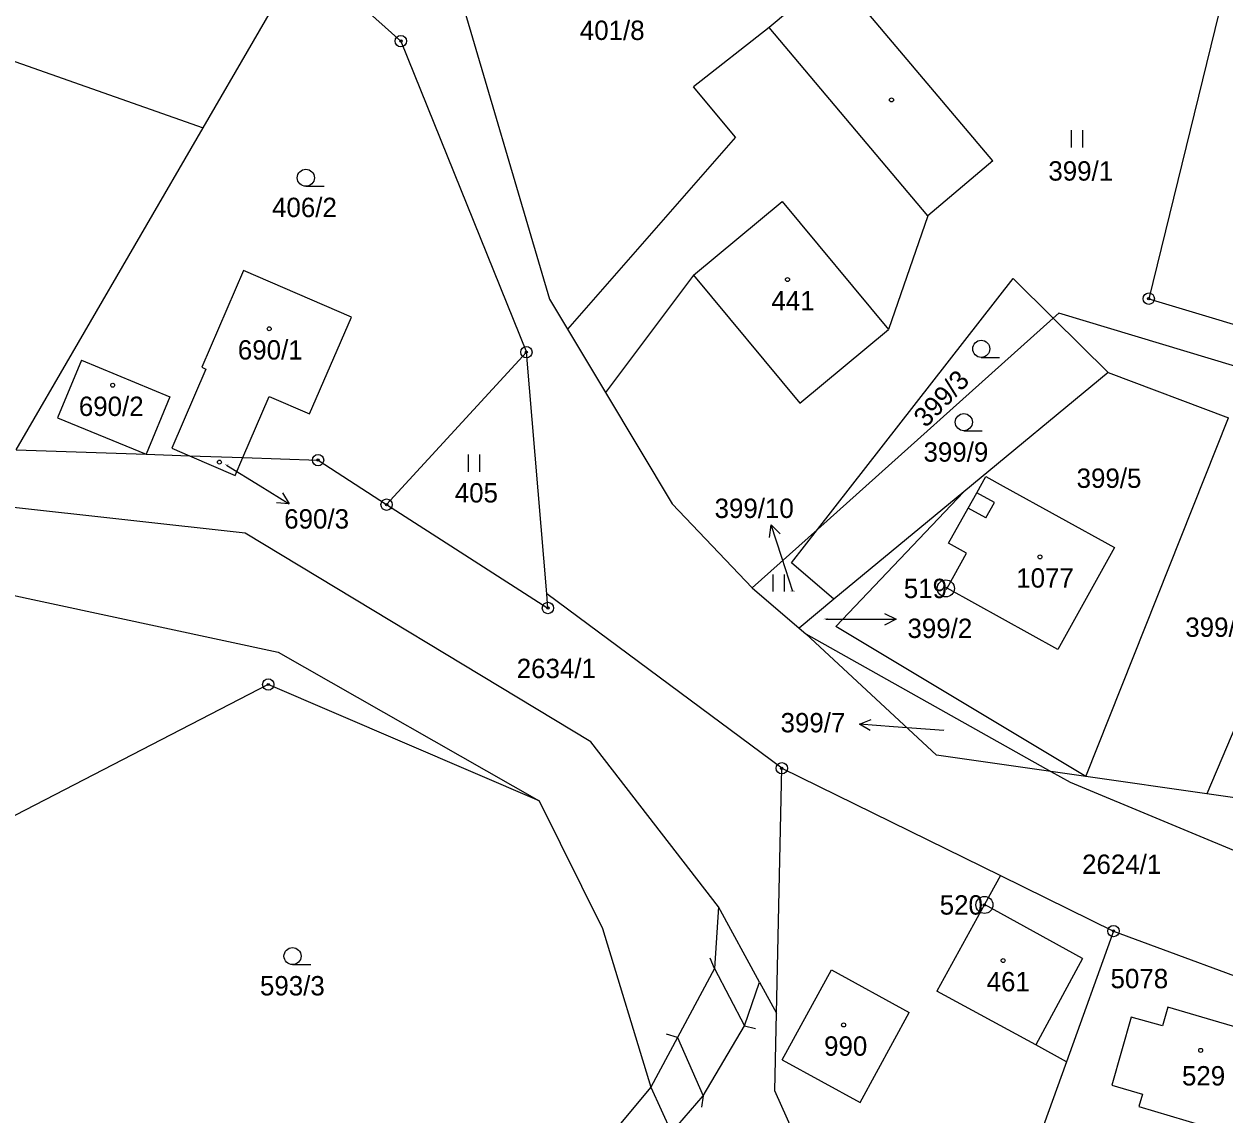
# Model space of a CAD drawing. Extents: x -439246 to -433691, y -1130252 to -1121148.
# Drawn here: x -437614.4 to -437509, y -1124136.2 to -1124040.5 of the extents above; entities that cross this region are included whole.
import ezdxf

# ---------------------------------------------------------------- set-up
doc = ezdxf.new("R2010")
doc.units = 0
for name, color, linetype in [('Vrstva 1', 7, 'Continuous'), ('Vrstva 16', 7, 'Continuous'), ('Vrstva 17', 7, 'Continuous'), ('Vrstva 18', 7, 'Continuous'), ('Vrstva 19', 7, 'Continuous'), ('Vrstva 24', 7, 'Continuous'), ('Vrstva 25', 7, 'Continuous'), ('Vrstva 26', 7, 'Continuous'), ('Vrstva 3', 7, 'Continuous'), ('Vrstva 37', 7, 'Continuous'), ('Vrstva 4', 7, 'Continuous')]:
    doc.layers.add(name, color=color, linetype=linetype)

msp = doc.modelspace()

# ---------------------------------------------------------------- linework, layer by layer
at = {"layer": 'Vrstva 1'}
for points in [[(-437507.31, -1124030.55), (-437515.65, -1124064.59)], [(-437598.67, -1124049.6), (-437589.83, -1124034.37)], [(-437589.83, -1124034.37), (-437581.3, -1124041.99)], [(-437576.65, -1124036.12), (-437568.26, -1124064.63)], [(-437543.27, -1124035.99), (-437548.98, -1124040.81)], [(-437529.34, -1124052.5), (-437543.27, -1124035.99)], [(-437622.36, -1124041.27), (-437598.67, -1124049.6)], [(-437548.98, -1124040.81), (-437555.6, -1124045.99)], [(-437581.3, -1124041.99), (-437570.28, -1124069.28)], [(-437551.93, -1124050.43), (-437555.6, -1124045.99)], [(-437615.06, -1124077.85), (-437598.67, -1124049.6)], [(-437551.93, -1124050.43), (-437566.66, -1124067.25)], [(-437529.34, -1124052.5), (-437535.05, -1124057.32)], [(-437535.05, -1124057.32), (-437538.5, -1124067.29)], [(-437595.11, -1124062.11), (-437598.78, -1124070.6)], [(-437585.63, -1124066.21), (-437595.11, -1124062.11)], [(-437555.6, -1124062.52), (-437563.34, -1124072.82)], [(-437555.6, -1124062.52), (-437546.27, -1124073.75)], [(-437544.73, -1124084.84), (-437527.55, -1124062.81)], [(-437527.55, -1124062.81), (-437524.03, -1124066.3)], [(-437568.26, -1124064.63), (-437566.66, -1124067.25)], [(-437515.65, -1124064.59), (-437476.75, -1124076.28)], [(-437589.32, -1124074.7), (-437585.63, -1124066.21)], [(-437524.03, -1124066.3), (-437544.73, -1124084.84)], [(-437523.55, -1124065.87), (-437524.03, -1124066.3)], [(-437524.03, -1124066.3), (-437519.22, -1124071.08)], [(-437479.06, -1124079.25), (-437523.55, -1124065.87)], [(-437566.66, -1124067.25), (-437563.34, -1124072.82)], [(-437546.27, -1124073.75), (-437538.5, -1124067.29)], [(-437609.35, -1124069.99), (-437611.43, -1124075.03)], [(-437609.35, -1124069.99), (-437601.59, -1124073.2)], [(-437570.28, -1124069.28), (-437582.55, -1124082.66)], [(-437568.49, -1124090.49), (-437570.28, -1124069.28)], [(-437598.42, -1124070.76), (-437601.42, -1124077.69)], [(-437598.78, -1124070.6), (-437598.42, -1124070.76)], [(-437519.22, -1124071.08), (-437531.88, -1124081.54)], [(-437519.22, -1124071.08), (-437508.64, -1124075.04)], [(-437601.59, -1124073.2), (-437603.67, -1124078.24)], [(-437595.18, -1124078.52), (-437592.86, -1124073.17)], [(-437592.86, -1124073.17), (-437589.32, -1124074.7)], [(-437563.34, -1124072.82), (-437557.48, -1124082.59)], [(-437611.43, -1124075.03), (-437603.67, -1124078.24)], [(-437521.17, -1124106.51), (-437508.64, -1124075.04)], [(-437615.06, -1124077.85), (-437603.67, -1124078.24)], [(-437603.67, -1124078.24), (-437599.85, -1124078.37)], [(-437601.42, -1124077.69), (-437599.85, -1124078.37)], [(-437599.85, -1124078.37), (-437595.86, -1124080.1)], [(-437599.85, -1124078.37), (-437595.18, -1124078.52)], [(-437595.86, -1124080.1), (-437595.18, -1124078.52)], [(-437595.18, -1124078.52), (-437588.57, -1124078.75)], [(-437588.57, -1124078.75), (-437582.55, -1124082.66)], [(-437498.29, -1124079.18), (-437510.55, -1124108.03)], [(-437594.98, -1124085.15), (-437636.74, -1124080.53)], [(-437530.75, -1124081.63), (-437529.96, -1124080.18)], [(-437529.96, -1124080.18), (-437528.42, -1124081.05)], [(-437531.88, -1124081.54), (-437543.28, -1124090.96)], [(-437543.13, -1124093.35), (-437531.88, -1124081.54)], [(-437531.5, -1124082.97), (-437530.75, -1124081.63)], [(-437528.42, -1124081.05), (-437518.65, -1124086.42)], [(-437582.55, -1124082.66), (-437568.39, -1124091.73)], [(-437557.48, -1124082.59), (-437550.45, -1124089.96)], [(-437533.22, -1124086.03), (-437531.5, -1124082.97)], [(-437564.63, -1124103.48), (-437594.98, -1124085.15)], [(-437544.73, -1124084.84), (-437550.45, -1124089.96)], [(-437547.01, -1124087.76), (-437544.73, -1124084.84)], [(-437636.68, -1124086.05), (-437592.08, -1124095.61)], [(-437533.35, -1124089.99), (-437531.65, -1124086.91)], [(-437531.65, -1124086.91), (-437533.22, -1124086.03)], [(-437518.65, -1124086.42), (-437523.64, -1124095.37)], [(-437543.28, -1124090.96), (-437547.01, -1124087.76)], [(-437550.45, -1124089.96), (-437546.33, -1124093.49)], [(-437523.64, -1124095.37), (-437533.35, -1124089.99)], [(-437547.86, -1124105.79), (-437568.49, -1124090.49)], [(-437568.39, -1124091.73), (-437568.49, -1124090.49)], [(-437543.28, -1124090.96), (-437546.33, -1124093.49)], [(-437546.33, -1124093.49), (-437545.76, -1124093.98)], [(-437534.29, -1124104.64), (-437545.76, -1124093.98)], [(-437545.76, -1124093.98), (-437524.24, -1124106.07)], [(-437521.17, -1124106.51), (-437543.13, -1124093.35)], [(-437592.08, -1124095.61), (-437569.16, -1124108.65)], [(-437592.94, -1124098.44), (-437619.4, -1124112.1)], [(-437569.16, -1124108.65), (-437592.94, -1124098.44)], [(-437553.43, -1124117.95), (-437564.63, -1124103.48)], [(-437524.24, -1124106.07), (-437534.29, -1124104.64)], [(-437548.32, -1124127.27), (-437547.86, -1124105.79)], [(-437547.86, -1124105.79), (-437528.66, -1124115.21)], [(-437524.24, -1124106.07), (-437522.55, -1124107.02)], [(-437521.17, -1124106.51), (-437524.24, -1124106.07)], [(-437510.55, -1124108.03), (-437521.17, -1124106.51)], [(-437522.55, -1124107.02), (-437497.19, -1124117.57)], [(-437569.16, -1124108.65), (-437563.6, -1124119.86)], [(-437496.29, -1124110.07), (-437510.55, -1124108.03)], [(-437528.66, -1124115.21), (-437530.07, -1124117.73)], [(-437528.66, -1124115.21), (-437518.74, -1124120.07)], [(-437549.81, -1124124.55), (-437553.43, -1124117.95)], [(-437530.07, -1124117.73), (-437534.25, -1124125.36)], [(-437563.6, -1124119.86), (-437559.36, -1124133.76)], [(-437518.74, -1124120.07), (-437522.88, -1124131.56)], [(-437518.74, -1124120.07), (-437503.2, -1124125.8)], [(-437547.83, -1124131.37), (-437543.51, -1124123.48)], [(-437543.51, -1124123.48), (-437536.67, -1124127.22)], [(-437549.81, -1124124.55), (-437548.32, -1124127.27)], [(-437525.56, -1124130.06), (-437534.25, -1124125.36)], [(-437504.32, -1124129.59), (-437513.96, -1124126.75), (-437514.44, -1124128.38), (-437517.19, -1124127.63), (-437518.89, -1124133.58), (-437516.21, -1124134.37), (-437516.53, -1124135.47), (-437506.89, -1124138.32)], [(-437548.46, -1124134.08), (-437548.32, -1124127.27)], [(-437540.99, -1124135.12), (-437536.67, -1124127.22)], [(-437522.88, -1124131.56), (-437525.56, -1124130.06)], [(-437547.83, -1124131.37), (-437540.99, -1124135.12)], [(-437522.88, -1124131.56), (-437524.89, -1124137.13)], [(-437559.36, -1124133.76), (-437565.4, -1124141.01)], [(-437559.36, -1124133.76), (-437557.54, -1124137.76)], [(-437534.8, -1124164.61), (-437548.46, -1124134.08)]]:
    msp.add_lwpolyline(points, dxfattribs=at)
at = {"layer": 'Vrstva 16'}
for p, q in [((-437593.66, -1124081.01), (-437591.11, -1124082.58)), ((-437547.86, -1124087.29), (-437548.78, -1124084.44)), ((-437540.83, -1124092.72), (-437537.83, -1124092.72)), ((-437538.06, -1124102.15), (-437541.05, -1124101.92))]:
    msp.add_line(p, q, dxfattribs=at)
for points in [[(-437596.6, -1124079.19), (-437593.66, -1124081.01)], [(-437591.7, -1124081.63), (-437591.11, -1124082.58), (-437592.22, -1124082.49)], [(-437548.95, -1124085.54), (-437548.78, -1124084.44), (-437548, -1124085.23)], [(-437546.89, -1124090.29), (-437547.86, -1124087.29)], [(-437543.99, -1124092.72), (-437540.83, -1124092.72)], [(-437538.83, -1124092.22), (-437537.83, -1124092.72), (-437538.83, -1124093.22)], [(-437540.09, -1124102.49), (-437541.05, -1124101.92), (-437540.02, -1124101.5)], [(-437533.65, -1124102.49), (-437538.06, -1124102.15)]]:
    msp.add_lwpolyline(points, dxfattribs=at)
at = {"layer": 'Vrstva 24'}
for centre, radius in [((-437581.3, -1124041.99), 0.5), ((-437581.3, -1124041.99), 0.1), ((-437515.65, -1124064.59), 0.5), ((-437515.65, -1124064.59), 0.1), ((-437570.28, -1124069.28), 0.5), ((-437570.28, -1124069.28), 0.1), ((-437588.57, -1124078.75), 0.5), ((-437588.57, -1124078.75), 0.1), ((-437582.55, -1124082.66), 0.5), ((-437582.55, -1124082.66), 0.1), ((-437533.46, -1124090.01), 0.75), ((-437533.46, -1124090.01), 0.1), ((-437568.39, -1124091.73), 0.5), ((-437568.39, -1124091.73), 0.1), ((-437592.94, -1124098.44), 0.5), ((-437592.94, -1124098.44), 0.1), ((-437547.86, -1124105.79), 0.5), ((-437547.86, -1124105.79), 0.1), ((-437530.07, -1124117.78), 0.75), ((-437530.07, -1124117.78), 0.1), ((-437518.74, -1124120.07), 0.5), ((-437518.74, -1124120.07), 0.1)]:
    msp.add_circle(centre, radius, dxfattribs=at)
at = {"layer": 'Vrstva 25'}
for p, q in [((-437522.42, -1124051.31), (-437522.42, -1124049.81)), ((-437521.42, -1124051.31), (-437521.42, -1124049.81)), ((-437589.64, -1124054.73), (-437588.04, -1124054.73)), ((-437530.35, -1124069.74), (-437528.75, -1124069.74)), ((-437531.88, -1124076.17), (-437530.28, -1124076.17)), ((-437575.37, -1124079.77), (-437575.37, -1124078.27)), ((-437574.37, -1124079.77), (-437574.37, -1124078.27)), ((-437548.62, -1124090.29), (-437548.62, -1124088.79)), ((-437547.62, -1124090.29), (-437547.62, -1124088.79)), ((-437590.81, -1124123.02), (-437589.21, -1124123.02))]:
    msp.add_line(p, q, dxfattribs=at)
for centre, radius in [((-437538.23, -1124047.15), 0.175), ((-437589.64, -1124053.98), 0.75), ((-437547.36, -1124062.91), 0.175), ((-437592.86, -1124067.23), 0.175), ((-437530.35, -1124068.99), 0.75), ((-437606.6, -1124072.18), 0.175), ((-437531.88, -1124075.42), 0.75), ((-437597.23, -1124078.93), 0.175), ((-437525.2, -1124087.24), 0.175), ((-437590.81, -1124122.27), 0.75), ((-437528.43, -1124122.66), 0.175), ((-437542.43, -1124128.31), 0.175), ((-437511.09, -1124130.54), 0.175)]:
    msp.add_circle(centre, radius, dxfattribs=at)
at = {"layer": 'Vrstva 26'}
for p, q in [((-437553.76, -1124123.37), (-437554.15, -1124122.45)), ((-437551.14, -1124128.39), (-437550.17, -1124128.61)), ((-437557.01, -1124129.4), (-437557.97, -1124129.13)), ((-437554.75, -1124134.52), (-437554.91, -1124135.51))]:
    msp.add_line(p, q, dxfattribs=at)
at = {"layer": 'Vrstva 3'}
for points in [[(-437555.6, -1124062.52), (-437547.84, -1124056.06)], [(-437547.84, -1124056.06), (-437538.5, -1124067.29)], [(-437595.11, -1124062.11), (-437598.78, -1124070.6)], [(-437585.63, -1124066.21), (-437595.11, -1124062.11)], [(-437555.6, -1124062.52), (-437546.27, -1124073.75)], [(-437589.32, -1124074.7), (-437585.63, -1124066.21)], [(-437546.27, -1124073.75), (-437538.5, -1124067.29)], [(-437609.35, -1124069.99), (-437611.43, -1124075.03)], [(-437609.35, -1124069.99), (-437601.59, -1124073.2)], [(-437598.42, -1124070.76), (-437601.42, -1124077.69)], [(-437598.78, -1124070.6), (-437598.42, -1124070.76)], [(-437601.59, -1124073.2), (-437603.67, -1124078.24)], [(-437595.18, -1124078.52), (-437592.86, -1124073.17)], [(-437592.86, -1124073.17), (-437589.32, -1124074.7)], [(-437611.43, -1124075.03), (-437603.67, -1124078.24)], [(-437601.42, -1124077.69), (-437599.85, -1124078.37)], [(-437599.85, -1124078.37), (-437595.86, -1124080.1)], [(-437595.86, -1124080.1), (-437595.18, -1124078.52)], [(-437530.75, -1124081.63), (-437529.96, -1124080.18)], [(-437529.96, -1124080.18), (-437528.42, -1124081.05)], [(-437529.2, -1124082.48), (-437530.75, -1124081.63)], [(-437528.42, -1124081.05), (-437518.65, -1124086.42)], [(-437529.95, -1124083.83), (-437529.2, -1124082.48)], [(-437533.22, -1124086.03), (-437531.5, -1124082.97)], [(-437529.95, -1124083.83), (-437531.5, -1124082.97)], [(-437533.35, -1124089.99), (-437531.65, -1124086.91)], [(-437531.65, -1124086.91), (-437533.22, -1124086.03)], [(-437518.65, -1124086.42), (-437523.64, -1124095.37)], [(-437523.64, -1124095.37), (-437533.35, -1124089.99)], [(-437530.07, -1124117.73), (-437534.25, -1124125.36)], [(-437521.47, -1124122.49), (-437530.07, -1124117.73)], [(-437521.47, -1124122.49), (-437525.56, -1124130.06)], [(-437547.83, -1124131.37), (-437543.51, -1124123.48)], [(-437543.51, -1124123.48), (-437536.67, -1124127.22)], [(-437525.56, -1124130.06), (-437534.25, -1124125.36)], [(-437504.32, -1124129.59), (-437513.96, -1124126.75), (-437514.44, -1124128.38), (-437517.19, -1124127.63), (-437518.89, -1124133.58), (-437516.21, -1124134.37), (-437516.53, -1124135.47), (-437506.89, -1124138.32)], [(-437540.99, -1124135.12), (-437536.67, -1124127.22)], [(-437547.83, -1124131.37), (-437540.99, -1124135.12)]]:
    msp.add_lwpolyline(points, dxfattribs=at)
at = {"layer": 'Vrstva 37'}
for centre in [(-437547.36, -1124062.91), (-437592.86, -1124067.23), (-437606.6, -1124072.18), (-437525.2, -1124087.24), (-437528.43, -1124122.66), (-437542.43, -1124128.31), (-437511.09, -1124130.54)]:
    msp.add_circle(centre, 0.175, dxfattribs=at)
at = {"layer": 'Vrstva 4'}
for points in [[(-437535.05, -1124057.32), (-437548.98, -1124040.81)], [(-437555.6, -1124062.52), (-437547.84, -1124056.06)], [(-437547.84, -1124056.06), (-437538.5, -1124067.29)], [(-437529.2, -1124082.48), (-437530.75, -1124081.63)], [(-437529.95, -1124083.83), (-437529.2, -1124082.48)], [(-437529.95, -1124083.83), (-437531.5, -1124082.97)], [(-437553.43, -1124117.95), (-437553.76, -1124123.37)], [(-437521.47, -1124122.49), (-437530.07, -1124117.73)], [(-437521.47, -1124122.49), (-437525.56, -1124130.06)], [(-437553.76, -1124123.37), (-437557.01, -1124129.4)], [(-437553.76, -1124123.37), (-437551.14, -1124128.39)], [(-437551.14, -1124128.39), (-437549.81, -1124124.55)], [(-437554.75, -1124134.52), (-437551.14, -1124128.39)], [(-437557.01, -1124129.4), (-437559.36, -1124133.76)], [(-437557.01, -1124129.4), (-437554.75, -1124134.52)], [(-437557.54, -1124137.76), (-437554.75, -1124134.52)]]:
    msp.add_lwpolyline(points, dxfattribs=at)

# ---------------------------------------------------------------- texts
at = {"layer": 'Vrstva 16'}
for s, p in [('399/10', (-437553.76, -1124083.83)), ('690/3', (-437591.54, -1124084.76)), ('399/2', (-437536.83, -1124094.36)), ('399/7', (-437547.97, -1124102.64)), ('2624/1', (-437521.5, -1124115.06))]:
    msp.add_text(s, height=1.7, dxfattribs=at).set_placement(p)
at = {"layer": 'Vrstva 17'}
for s, p in [('519', (-437537.15, -1124090.86)), ('520', (-437534, -1124118.63))]:
    msp.add_text(s, height=1.7, dxfattribs=at).set_placement(p)
at = {"layer": 'Vrstva 18'}
for s, height, p in [('401/8', 1.7, (-437565.59, -1124041.89)), ('399/1', 1.7, (-437524.46, -1124054.23)), ('406/2', 1.7, (-437592.61, -1124057.43)), ('399/9', 1.7, (-437535.42, -1124078.89)), ('399/5', 1.7, (-437521.98, -1124081.19)), ('405', 1.7, (-437576.57, -1124082.47)), ('399/10', 0.1, (-437547.11, -1124090.29)), ('399/2', 0.1, (-437544.18, -1124092.72)), ('399/4', 1.7, (-437512.44, -1124094.26)), ('2634/1', 1.7, (-437571.13, -1124097.88)), ('399/7', 0.1, (-437533.84, -1124102.5)), ('5078', 1.7, (-437519, -1124125.09)), ('593/3', 1.7, (-437593.67, -1124125.72))]:
    msp.add_text(s, height=height, dxfattribs=at).set_placement(p)
msp.add_text('399/3', height=1.7, rotation=46.1756, dxfattribs=at).set_placement((-437535.22, -1124075.98))
at = {"layer": 'Vrstva 19'}
for s, height, p in [('441', 1.7, (-437548.77, -1124065.61)), ('690/1', 1.7, (-437595.61, -1124069.93)), ('690/2', 1.7, (-437609.57, -1124074.88)), ('690/3', 0.1, (-437596.79, -1124079.19)), ('1077', 1.7, (-437527.28, -1124089.94)), ('461', 1.7, (-437529.88, -1124125.36)), ('990', 1.7, (-437544.15, -1124131.01)), ('529', 1.7, (-437512.73, -1124133.62))]:
    msp.add_text(s, height=height, dxfattribs=at).set_placement(p)

doc.saveas('drawing.dxf')
